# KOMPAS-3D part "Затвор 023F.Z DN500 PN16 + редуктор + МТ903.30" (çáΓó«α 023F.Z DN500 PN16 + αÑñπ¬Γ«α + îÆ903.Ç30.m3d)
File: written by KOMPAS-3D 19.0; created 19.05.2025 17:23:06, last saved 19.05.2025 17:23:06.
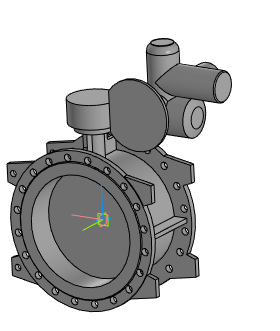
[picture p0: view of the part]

Document properties: Полное имя файла: Затвор 023F.Z DN500 PN16 + редуктор + МТ903.30.a3d

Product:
- Part/product: Затвор 023F.Z DN500 PN16 + редуктор + МТ903.30
    Масса: 479.312

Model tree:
1. Операция без истории:1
